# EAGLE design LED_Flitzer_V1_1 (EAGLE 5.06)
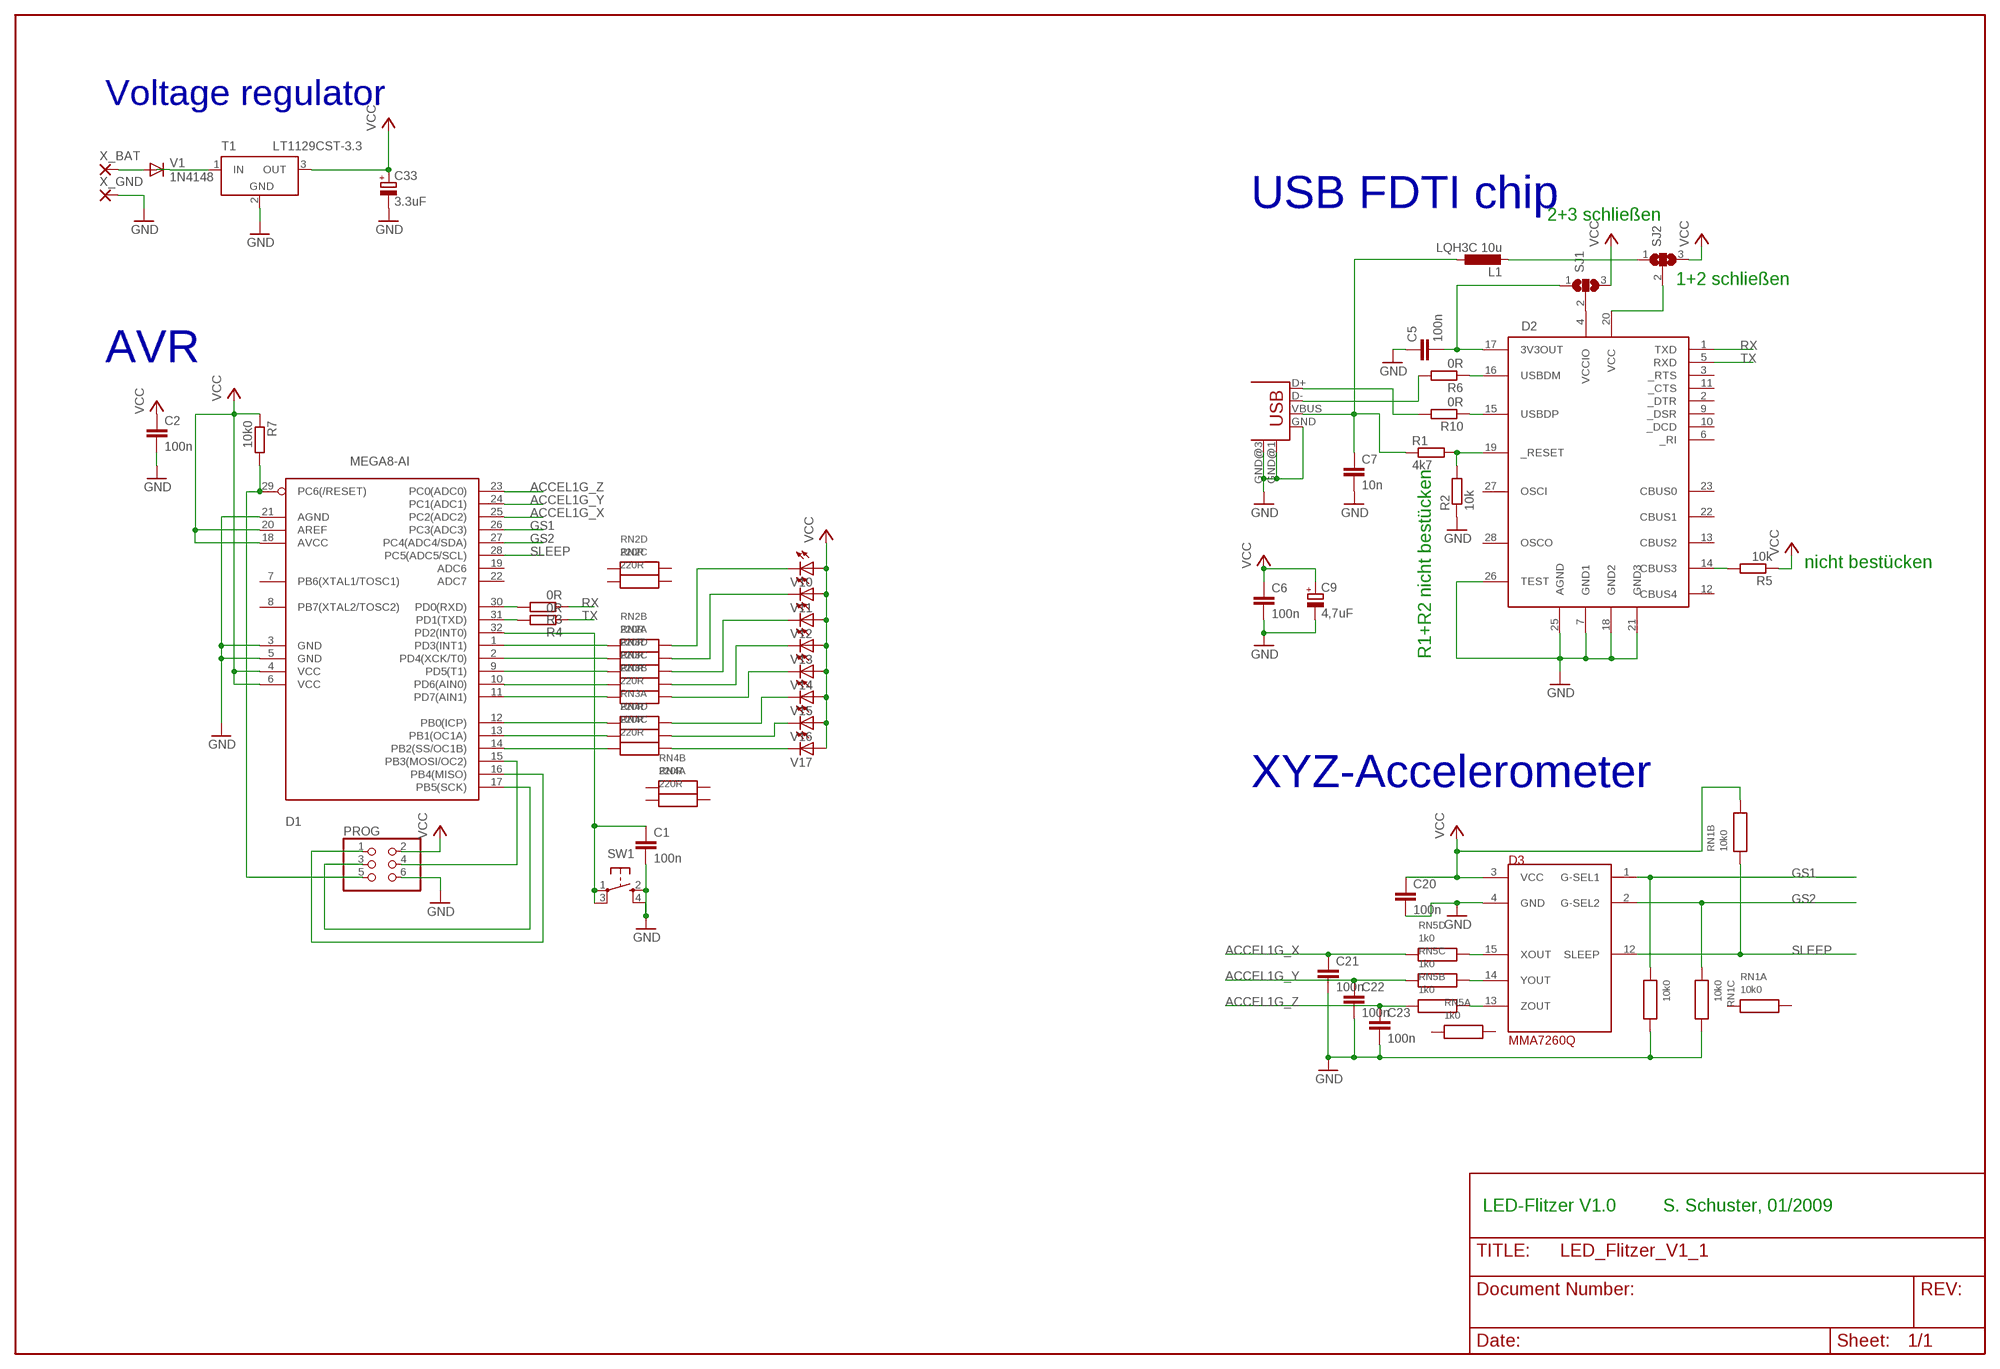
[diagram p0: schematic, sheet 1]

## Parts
C1  100n  C-EUC1206  [C1206]
C2  100n  C-EUC1206  [C1206]
C5  100n  C-EUC1206  [C1206]
C6  100n  C-EUC1206  [C1206]
C7  10n  C-EUC1206  [C1206]
C9  4,7uF  CPOL-EUCT6032  [CT6032]
C20  100n  C-EUC1206  [C1206]
C21  100n  C-EUC1206  [C1206]
C22  100n  C-EUC1206  [C1206]
C23  100n  C-EUC1206  [C1206]
C33  3.3uF  CPOL-EUCT6032  [CT6032]
D1  MEGA8-AI  [TQFP32-08]
D2  FT232RL  [SSOP28DB]
D3  MMA7260Q  [QFN16]
L1  LQH3C 10u  L-EUL3225P  [L3225P]
PROG  PINHD-2X3  [2X03]
R1  4k7  R-EU_M1206  [M1206]
R2  10k  R-EU_M1206  [M1206]
R3  0R  R-EU_M1206  [M1206]
R4  0R  R-EU_M1206  [M1206]
R5  10k  R-EU_M1206  [M1206]
R6  0R  R-EU_M1206  [M1206]
R7  10k0  R-EU_M1206  [M1206]
R10  0R  R-EU_M1206  [M1206]
RN1  10k0  4X1-12061206  [1206]
RN2  220R  4X1-12061206  [1206]
RN3  220R  4X1-12061206  [1206]
RN4  220R  4X1-12061206  [1206]
RN5  1k0  4X1-12061206  [1206]
SJ1  SJ2W  [SJ_2]
SJ2  SJ2W  [SJ_2]
SW1  CK_TACTSWITCHJ-LEAD  [CK_KT11_JM]
T1  LT1129CST-3.3  LT1129CST5  [SOT223]
USB1  USB BWM SMD  USB-MB-S  [USB-MB-S]
V1  1N4148  [DO35-10]
V10  LEDCHIPLED_1206  [CHIPLED_1206]
V11  LEDCHIPLED_1206  [CHIPLED_1206]
V12  LEDCHIPLED_1206  [CHIPLED_1206]
V13  LEDCHIPLED_1206  [CHIPLED_1206]
V14  LEDCHIPLED_1206  [CHIPLED_1206]
V15  LEDCHIPLED_1206  [CHIPLED_1206]
V16  LEDCHIPLED_1206  [CHIPLED_1206]
V17  LEDCHIPLED_1206  [CHIPLED_1206]
X_BAT  2,15/1,0  [2,15/1,0]
X_GND  2,15/1,0  [2,15/1,0]

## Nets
ACCEL1G_X: C21.1 D1.25(PC2(ADC2)) RN5.R4A(D:A)
ACCEL1G_Y: C22.1 D1.24(PC1(ADC1)) RN5.R3A(C:A)
ACCEL1G_Z: C23.1 D1.23(PC0(ADC0)) RN5.R2A(B:A)
GND [power]: C1.2 C2.2 C5.1 C6.2 C7.2 C9.- C20.2 C21.2 C22.2 C23.2 C33.- D1.3(GND) D1.5(GND) D1.21(AGND) D2.7(GND1) D2.18(GND2) D2.21(GND3) D2.25(AGND) D2.26(TEST) D3.4(GND) PROG.6 R2.1 RN1.R3B(C:B) RN1.R4B(D:B) SW1.2(S) SW1.4(S1) T1.2(GND) USB1.GND USB1.GND@1(GND) USB1.GND@3(GND) X_GND.1(P)
GS1: D1.26(PC3(ADC3)) D3.1(G-SEL1) RN1.R4A(D:A)
GS2: D1.27(PC4(ADC4/SDA)) D3.2(G-SEL2) RN1.R3A(C:A)
N$3: R6.2 USB1.D-
N$4: R10.2 USB1.D+
N$5: D1.30(PD0(RXD)) R3.2
N$6: D1.31(PD1(TXD)) R4.2
N$7: D1.1(PD3(INT1)) RN2.R2A(B:A)
N$8: D1.2(PD4(XCK/T0)) RN2.R1A(A:A)
N$9: D1.9(PD5(T1)) RN3.R4A(D:A)
N$10: D1.10(PD6(AIN0)) RN3.R3A(C:A)
N$11: D1.11(PD7(AIN1)) RN3.R2A(B:A)
N$12: D1.12(PB0(ICP)) RN3.R1A(A:A)
N$14: D2.20(VCC) SJ2.2
N$15: D1.15(PB3(MOSI/OC2)) PROG.4
N$16: D1.17(PB5(SCK)) PROG.3
N$17: C1.1 D1.32(PD2(INT0)) SW1.1(P) SW1.3(P1)
N$18: D1.29(PC6(/RESET)) PROG.5 R7.2
N$19: D1.16(PB4(MISO)) PROG.1
N$20: D1.13(PB1(OC1A)) RN4.R4A(D:A)
N$21: D1.14(PB2(SS/OC1B)) RN4.R3A(C:A)
N$24: D2.19(_RESET) R1.2 R2.2
N$27: RN2.R2B(B:B) V10.C
N$29: RN3.R4B(D:B) V12.C
N$30: RN3.R3B(C:B) V13.C
N$31: RN3.R2B(B:B) V14.C
N$32: RN3.R1B(A:B) V15.C
N$33: RN4.R4B(D:B) V16.C
N$34: RN4.R3B(C:B) V17.C
N$35: C7.1 L1.1 R1.1 USB1.VBUS
N$39: C5.2 D2.17(3V3OUT) SJ1.1
N$40: D2.14(CBUS3) R5.2
N$41: D2.16(USBDM) R6.1
N$42: D2.15(USBDP) R10.1
N$43 [power]: V1.A X_BAT.1(P)
N$44: L1.2 SJ2.1
N$45: D2.4(VCCIO) SJ1.2
N$46 [power]: T1.1(IN) V1.C
N$72: D3.15(XOUT) RN5.R4B(D:B)
N$73: D3.14(YOUT) RN5.R3B(C:B)
N$74: D3.13(ZOUT) RN5.R2B(B:B)
RX: D2.1(TXD) R3.1
SLEEP: D1.28(PC5(ADC5/SCL)) D3.12(SLEEP) RN1.R2A(B:A)
TX: D2.5(RXD) R4.1
V11: RN2.R1B(A:B) V11.C
VCC [power]: C2.1 C6.1 C9.+ C20.1 C33.+ D1.4(VCC) D1.6(VCC) D1.18(AVCC) D1.20(AREF) D3.3(VCC) PROG.2 R5.1 R7.1 RN1.R2B(B:B) SJ1.3 SJ2.3 T1.3(OUT) V10.A V11.A V12.A V13.A V14.A V15.A V16.A V17.A
Unconnected: D1.7(PB6(XTAL1/TOSC1)) D1.8(PB7(XTAL2/TOSC2)) D1.19(ADC6) D1.22(ADC7) D2.2(_DTR) D2.3(_RTS) D2.6(_RI) D2.9(_DSR) D2.10(_DCD) D2.11(_CTS) D2.12(CBUS4) D2.13(CBUS2) D2.22(CBUS1) D2.23(CBUS0) D2.27(OSCI) D2.28(OSCO) RN1.R1A(A:A) RN1.R1B(A:B) RN2.R3A(C:A) RN2.R3B(C:B) RN2.R4A(D:A) RN2.R4B(D:B) RN4.R1A(A:A) RN4.R1B(A:B) RN4.R2A(B:A) RN4.R2B(B:B) RN5.R1A(A:A) RN5.R1B(A:B)

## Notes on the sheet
- Voltage regulator
- USB FDTI chip
- 2+3 schließen
- 1+2 schließen
- AVR
- nicht bestücken
- R1+R2 nicht bestücken
- XYZ-Accelerometer
- LED-Flitzer V1.0 | S. Schuster, 01/2009

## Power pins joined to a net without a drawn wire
GND: T1.4(GND)

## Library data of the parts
C1 C2 C5-C7 C20-C23 = rcl:C-EU: CAPACITOR, European symbol
C9 C33 = rcl:CPOL-EU: POLARIZED CAPACITOR, European symbol
D1 = proj:MEGA8: MICROCONTROLLER 8 Kbytes FLASH 1 kbytes SRAM 512 bytes EEPROM USART 6-channel 10 bit ADC 2-channel 8 bit ADC
D2 = ftdichip:FT232RL: USB UART 4th Generation USB UART (USB <-> Serial) Controller
D3 = my_freescale_mma:MMA7260Q
L1 = rcl:L-EU: INDUCTOR, European symbol
PROG = proj:PINHD-2X3: PIN HEADER
R1-R7 R10 = rcl:R-EU_: RESISTOR, European symbol
RN1-RN5 = arrays:4X1-1206
SJ1 SJ2 = jumper:SJ2W: SMD solder JUMPER
SW1 = proj:CK_TACTSWITCH: C&K tactile switches
T1 = linear-technology:LT1129CST5: VOLTAGE REGULATOR with shutdown
USB1 = con-usb-2:USB: USB Connectors
V1 = diode:1N4148: DIODE
V10-V17 = proj:LED: LED
X_BAT X_GND = wirepad:2,15/1,0: THROUGH-HOLE PAD

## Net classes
1 power: width 0.305 mm, drill 0.61 mm

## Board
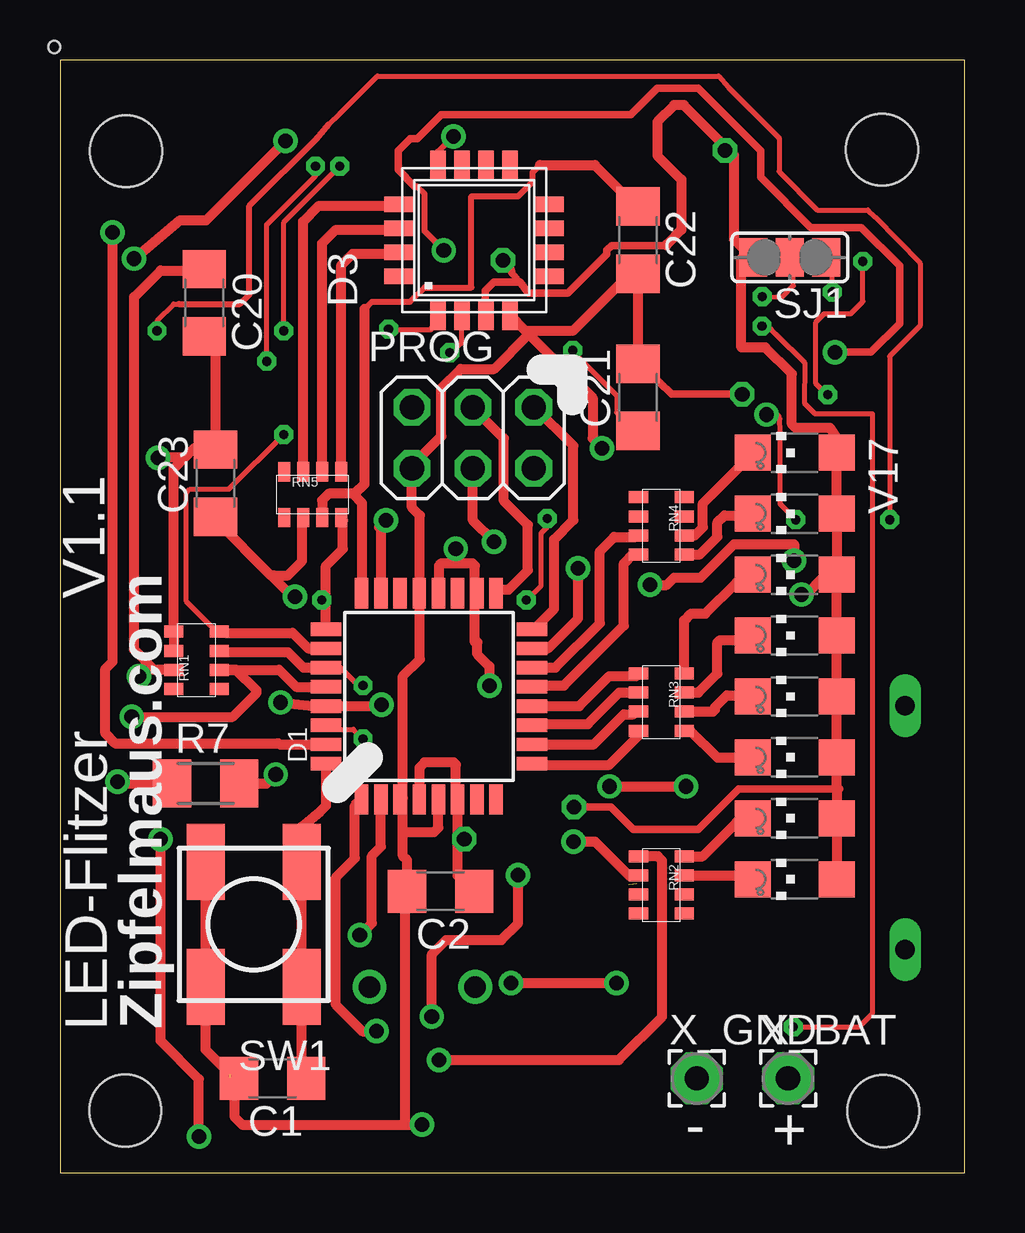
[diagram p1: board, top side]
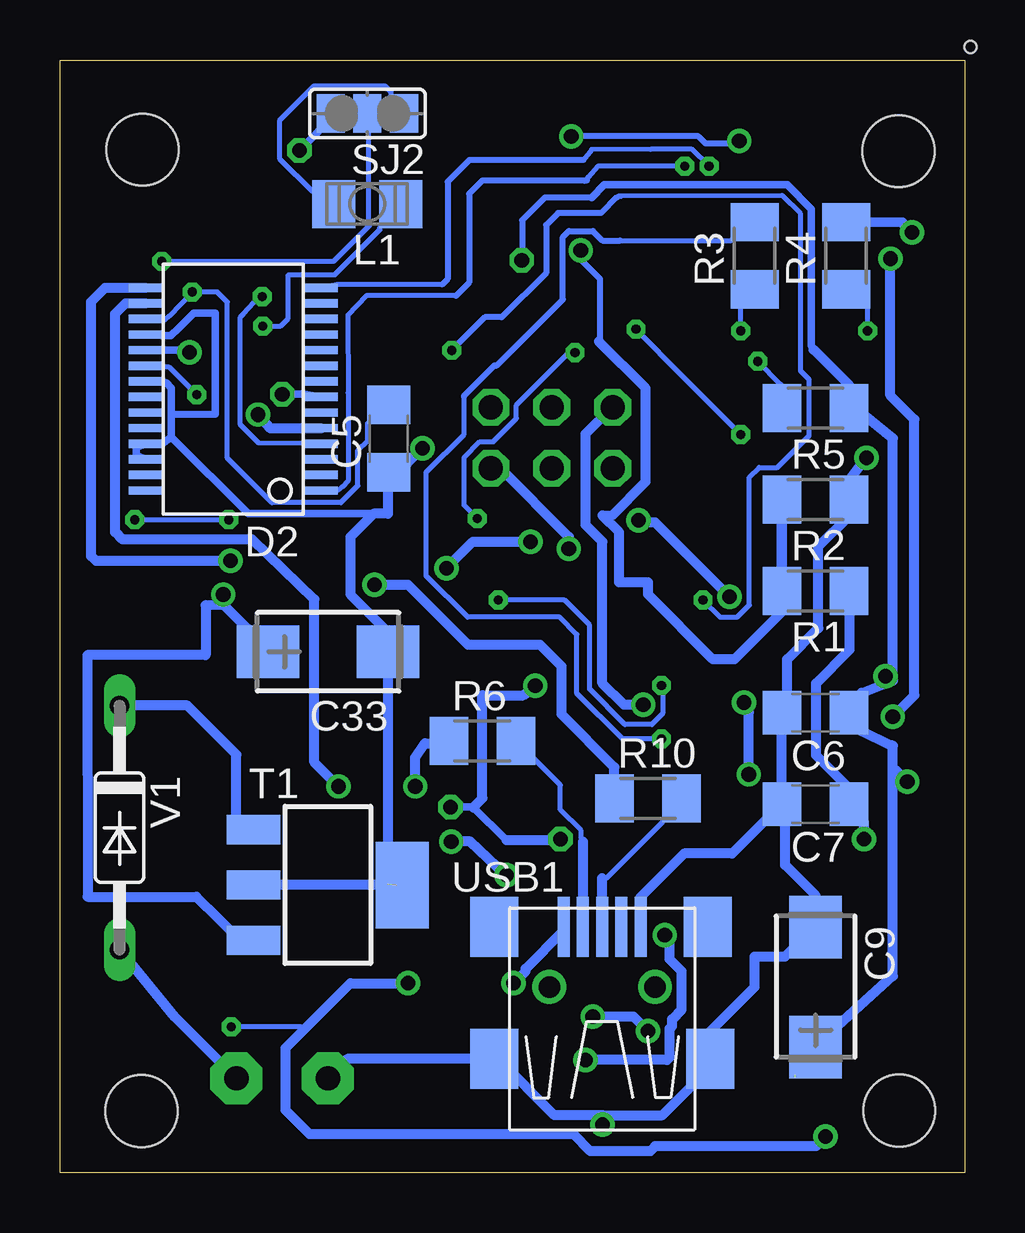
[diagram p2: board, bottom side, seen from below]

Size 37.69 x 46.38 mm. Coordinates in mm from the lower left corner, seen from the top.
Outline: 37.69,0 37.69,46.38 0,46.38 0,0 37.69,0
Copper layers (1*16): Top 0.035mm / dielectric 1.5mm / Bottom 0.035mm
Design rules "default": minimum track width 8mil, minimum drill 15mil, track to track 8mil, track to pad 8mil, pad to pad 8mil, via to via 8mil, smd to smd 8mil, copper to edge 40mil, drill to drill 8mil, minimum pad ring 10mil, minimum via ring 8mil, stop-mask expansion 4mil, vias tented up to drill 25mil, thermal gap 10mil
Holes 3 mm at 34.3,2.57 2.72,2.59 2.75,42.58 34.25,42.64
Holes 0.5 mm at -0.24,46.93

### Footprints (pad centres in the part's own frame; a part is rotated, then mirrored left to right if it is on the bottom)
C1206 = smd 1.6 x 1.8: 1 -1.4,0; 2 1.4,0
CT6032 = smd 2.6 x 2.2: + 2.5,0; - -2.5,0
TQFP32-08 = smd 1.27 x 0.559: 1 -4.293,2.8; 2 -4.293,2; 3 -4.293,1.2; 4 -4.293,0.4; 5 -4.293,-0.4; 6 -4.293,-1.2; 7 -4.293,-2; 8 -4.293,-2.8; 17 4.293,-2.8; 18 4.293,-2; 19 4.293,-1.2; 20 4.293,-0.4; 21 4.293,0.4; 22 4.293,1.2; 23 4.293,2; 24 4.293,2.8 | smd 0.559 x 1.27: 9 -2.8,-4.293; 10 -2,-4.293; 11 -1.2,-4.293; 12 -0.4,-4.293; 13 0.4,-4.293; 14 1.2,-4.293; 15 2,-4.293; 16 2.8,-4.293; 25 2.8,4.293; 26 2,4.293; 27 1.2,4.293; 28 0.4,4.293; 29 -0.4,4.293; 30 -1.2,4.293; 31 -2,4.293; 32 -2.8,4.293
SSOP28DB = smd 0.348 x 1.397: 1 -4.225,-3.656; 2 -3.575,-3.656; 3 -2.925,-3.656; 4 -2.275,-3.656; 5 -1.625,-3.656; 6 -0.975,-3.656; 7 -0.325,-3.656; 8 0.325,-3.656; 9 0.975,-3.656; 10 1.625,-3.656; 11 2.275,-3.656; 12 2.925,-3.656; 13 3.575,-3.656; 14 4.225,-3.656; 15 4.225,3.656; 16 3.575,3.656; 17 2.925,3.656; 18 2.275,3.656; 19 1.625,3.656; 20 0.975,3.656; 21 0.325,3.656; 22 -0.325,3.656; 23 -0.975,3.656; 24 -1.625,3.656; 25 -2.275,3.656; 26 -2.925,3.656; 27 -3.575,3.656; 28 -4.225,3.656
QFN16 = smd 1.27 x 0.635: 1 -3.1,1.5; 2 -3.1,0.5; 3 -3.1,-0.5; 4 -3.1,-1.5; 9 3.1,-1.5; 10 3.1,-0.5; 11 3.1,0.5; 12 3.1,1.5 | smd 0.635 x 1.27: 5 -1.5,-3.1; 6 -0.5,-3.1; 7 0.5,-3.1; 8 1.5,-3.1; 13 1.5,3.1; 14 0.5,3.1; 15 -0.5,3.1; 16 -1.5,3.1
L3225P = smd 1.8 x 2: 1 -1.4,0; 2 1.4,0
2X03 = drill 1.016 octagon: 1 -2.54,-1.27; 2 -2.54,1.27; 3 0,-1.27; 4 0,1.27; 5 2.54,-1.27; 6 2.54,1.27
M1206 = smd 1.6 x 2: 1 -1.4,0; 2 1.4,0
1206 = smd 0.5 x 0.8: R1A 0.318,-0.159; R1B 0.318,1.746; R2A 1.111,-0.159; R2B 1.111,1.746; R3A 1.905,-0.159; R3B 1.905,1.746; R4A 2.699,-0.159; R4B 2.699,1.746
SJ_2 = smd 1.168 x 1.6: 1 -1.524,0; 2 0,0; 3 1.524,0
CK_KT11_JM = smd 3.175 x 1.587: 1 -2.603,2; 2 -2.603,-2; 3 2.603,2; 4 2.603,-2
SOT223 = smd 1.219 x 2.235: 1 -2.311,-3.099; 2 0,-3.099; 3 2.311,-3.099 | smd 3.6 x 2.2: 4 0,3.099
USB-MB-S = smd 2.5 x 0.5: D+ 2.5,0; D- 2.5,0.8; GND 2.5,-1.6; ID 2.5,-0.8; VBUS 2.5,1.6 | smd 2.5 x 2: GND@1 -3,4.5; GND@2 2.5,4.5; GND@3 -3,-4.5; GND@4 2.5,-4.4 | drill 0.9 round: P$5 0,2.2; P$6 0,-2.2
DO35-10 = drill 0.813 long: A 5.08,0; C -5.08,0
CHIPLED_1206 = smd 1.5 x 1.5: A 0,-1.75; C 0,1.75
2,15/1,0 = drill 1.016 pad 2.159 octagon: 1 0,0

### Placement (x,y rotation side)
C1  8.86,3.93 180 top
C2  15.86,11.73 180 top
C5  23.99,30.6 90 bottom
C6  6.21,19.17 180 bottom
C7  6.21,15.36 180 bottom
C9  6.21,7.74 270 bottom
C20  6.01,36.26 270 top
C21  24.08,32.32 90 top
C22  24.08,38.87 270 top
C23  6.48,28.74 90 top
C33  26.53,21.71 180 bottom
D1  15.37,19.85 90 top
D2  30.47,32.66 90 bottom
D3  17.25,38.86 90 top
L1  24.89,40.38 180 bottom
PROG  17.2,30.63 180 top
R1  6.21,24.25 180 bottom
R2  6.21,28.06 180 bottom
R3  8.75,38.22 90 bottom
R4  4.94,38.22 90 bottom
R5  6.21,31.87 180 bottom
R6  20.09,17.99 0 bottom
R7  6.07,16.22 0 top
R10  13.19,15.6 0 bottom
RN1  6.48,19.85 90 top
RN2  24.26,13.5 270 top
RN3  24.26,21.12 270 top
RN4  24.26,28.47 270 top
RN5  9.02,27.47 0 top
SJ1  30.41,38.15 180 top
SJ2  24.88,44.15 180 bottom
SW1  8.07,10.35 270 top
T1  26.53,11.99 270 bottom
USB1  15.1,7.74 90 bottom
V1  35.21,14.38 270 bottom
V10  30.61,12.23 90 top
V11  30.61,14.77 90 top
V12  30.61,17.31 90 top
V13  30.61,19.85 90 top
V14  30.61,22.39 90 top
V15  30.61,24.93 90 top
V16  30.61,27.47 90 top
V17  30.61,30.01 90 top
X_BAT  30.34,3.93 0 top
X_GND  26.53,3.93 0 top

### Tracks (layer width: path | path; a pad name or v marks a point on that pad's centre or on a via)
ACCEL1G_X  (via drill 0.38)
  Top 0.203: v21.36,34.28 21.36,34.23 23.19,32.4 23.19,31.69 C21.1 | 11.08,23.86 v10.9,23.86
  Top 0.406: D1.25 11.08,23.86 11.08,25.29 11.79,26 11.79,27.2 11.72,27.27 RN5.R4A
  Bottom 0.203: 14.48,40.66 14.44,40.7 14.31,40.7 7.6,40.73 6.84,39.97 6.84,33.41 6.48,33.06 6.48,30.72 7.8,29.4 8.56,29.4 8.97,28.99 8.97,23.66 9.48,23.15 10.19,23.15 v10.9,23.86
  Bottom 0.254: 14.48,40.66 15.14,40 16.94,40 17.44,39.5 17.44,37.5 19.29,35.65 19.99,35.65 v21.36,34.28
ACCEL1G_Y
  Top 0.254: 12.69,36 12.99,36.3 14.59,36.3 15.19,36.9 17.14,36.9 17.14,40.7 19.09,40.7 19.69,41.3 19.69,41.7 19.99,42
  Top 0.406: 12.55,24.14 D1.24 12.57,24.28 12.59,24.3 12.59,27.9 12.19,28.3 | RN5.R3A 10.93,28.04 11.19,28.3 12.19,28.3 | 12.19,28.3 12.29,28.3 12.69,28.7 12.69,36 | C22.1 24.02,40.27 22.29,42 19.99,42
ACCEL1G_Z  (via drill 0.61)
  Top 0.406: C23.1 6.48,27.21 8.79,24.9 8.89,24.9 | 8.89,24.9 9.49,24.9 10.09,25.5 10.09,27.3 10.1,27.31 RN5.R2A | D1.23 13.37,26.9 13.29,26.9 v13.59,27.2 | 8.89,24.9 8.89,24.8 9.69,24 v9.79,24
  Bottom 0.406: v13.59,27.2 13.59,27.1 12.89,27.1 v9.79,24
GND  (via drill 0.61)  (2 unrouted)
  Top 0.305: v28.43,32.45 25.48,32.45 24.97,32.96 C21.2
  Top 0.406: C20.2 6.01,34.82 5.99,34.8 6.48,34.31 C23.2 | RN1.R3B 4.73,22.46 4.69,22.5 RN1.R4B 4.73,29.34 5.19,29.8 | C23.2 6.65,30.14 | C23.2 6.48,30.19 6.49,30.2 5.59,30.2 5.19,29.8 | 5.19,29.8 v4.09,29.8 | 24.09,37.5 24.08,37.49 C22.2 | C22.2 C21.2 | C22.2 23.76,37.47 21.39,35.1 19.39,35.1 | v22.59,30.2 22.19,30.6 22.19,32.3 19.54,34.95 | D3.4 18.75,35.74 19.39,35.1 | 19.54,34.95 19.39,35.1 | 19.54,34.95 18.09,33.5 16.69,33.5 15.89,32.7 15.89,30.7 14.66,29.47 PROG.6 14.66,27.73 14.99,27.4 14.99,24 | 14.97,24.02 D1.21 14.93,24.04 14.99,24 | 14.97,24.02 14.89,24.1 14.89,24.2 14.99,24.1 14.99,24 | 14.99,24 14.97,24.02 | 14.99,24 14.99,21.4 14.29,20.7 14.29,15.6 | D1.3 14.25,15.56 14.29,15.6 | D1.5 15.77,14.38 15.59,14.2 14.29,14.2 | 14.29,14.2 14.29,15.6 | 14.29,14.2 14.29,13.2 14.46,13.03 C2.2 14.46,11.99 14.32,12.13 14.32,11.87 14.39,11.6 14.39,2 | 6.07,12.8 SW1.2 | 6.07,12.8 6.09,12.8 | 6.07,12.8 6.07,7.62 6.09,7.6 6.07,7.6 | 14.39,2 v15.09,2 | 14.39,2 7.59,2 7.29,2.3 7.29,3.6 6.99,3.9 7.07,3.98 | 6.07,7.6 SW1.4 | 6.07,7.6 6.07,5.12 7.09,4.1 7.07,4.08 7.22,3.93 C1.2
  Bottom 0.305: D2.18 33.46,34.89 33.09,34.89 32.74,35.2 32.11,35.83 31.23,35.83 31.23,31.62 33.05,31.6 33.05,32.7 | D2.26 34.52,29.91 34.52,30.21 D2.25 33.46,30.36 33.05,30.67 | D2.21 33.46,33.01 33.25,32.91 33.05,32.7 | D2.7 27.51,32.45 v28.43,32.45 | 33.05,30.67 33.05,32.7 | 33.05,30.67 29.85,27.47 24.03,27.47
  Bottom 0.406: 24.03,12.04 C33.- 24.03,22.54 25.59,24.1 25.59,26.5 24.62,27.47 24.03,27.47 24.03,29 | C5.1 23.99,29.3 24.03,29.26 24.03,29 | v4.09,29.8 4.81,28.88 R2.1 4.81,27.38 6.09,26.1 6.09,22.7 7.39,21.4 7.39,19.4 7.49,19.3 7.49,19.17 | 24.03,29 23.79,29 v22.59,30.2 | 7.49,19.17 C6.2 | 7.49,19.17 7.48,19.17 7.61,19.04 C7.2 7.48,15.36 7.48,15.3 | USB1.GND 13.5,11.49 11.69,13.3 9.69,13.3 7.69,15.3 7.48,15.3 | 7.48,15.3 7.48,12.82 6.21,11.55 6.21,10.28 | 6.21,10.28 C9.- | 6.21,10.28 7.48,9.01 8.75,9.01 8.75,7.74 10.6,5.89 USB1.GND@3 10.6,4.39 12.59,2.4 15.09,2.4 | X_GND.1 25.72,4.74 USB1.GND@1 | 20.18,5.2 19.72,4.74 USB1.GND@1 | USB1.GND@1 19.43,4.74 17.09,2.4 15.09,2.4 | v15.09,2 15.09,2.4 | 29.63,12.14 29.69,12.2 | 29.63,12.14 T1.2 | 29.63,12.14 29.48,11.99 23.69,11.99 | 23.69,11.99 23.69,11.7 | T1.4 23.69,11.99
GS1  (via drill 0.38)
  Top 0.203: v13.69,35.16 13.69,35.1 13.73,35.14 15.47,35.14 D3.1 | v9.33,30.77 7.04,28.49 5.41,28.49 5.26,28.33 5.26,23.81 6.28,22.8 RN1.R4A
  Top 0.406: D1.26 10.34,21.85 9.69,22.5 6.89,22.5 6.79,22.6 6.74,22.55 RN1.R4A
  Bottom 0.203: v13.69,35.16 11.71,33.16 v9.33,30.77
GS2  (via drill 0.38)
  Top 0.203: v16.23,34.18 16.74,34.58 16.74,35.34 D3.2 | v20.3,27.27 20.3,26.91 20.04,26.66 20.04,24.47 v19.43,23.86 | v12.63,20.31 12.42,20.31 11.66,21.07 D1.27
  Top 0.406: RN1.R3A 6.64,21.75 6.59,21.7 9.49,21.7 10.14,21.05 D1.27 11.24,21.05 11.29,21.1
  Bottom 0.203: v16.23,34.18 16.49,34.18 18.67,31.99 18.67,31.43 19.64,30.47 20.2,30.47 20.86,29.81 20.86,27.83 v20.3,27.27 | v19.43,23.86 16.67,23.86 15.62,22.82 15.62,20.16 14.15,18.68 13.03,18.68 12.58,19.14 12.58,20.26 v12.63,20.31
N$3
  Bottom 0.203: R6.2 16.84,16.15 16.84,15.13 15.98,14.26 15.98,13.96 15.89,13.8
  Bottom 0.406: USB1.D- 15.95,10.24 15.89,10.3 15.89,13.8
N$4
  Bottom 0.203: R10.2 12.58,14.62 14.91,12.28 15.1,12.28
  Bottom 0.406: USB1.D+ 15.1,12.28
N$5  (via drill 0.38)
  Top 0.203: v12.63,18.07 12.22,18.48 11.66,18.48 D1.30
  Bottom 0.203: v12.63,18.07 14.25,18.07 16.15,19.97 16.15,22.44 16.87,23.15 20.7,23.15 22.43,24.88 22.43,29.2 20.86,30.77 20.86,32.35 | 14.35,38.85 9.73,38.85 R3.2
  Bottom 0.254: 14.35,38.85 15.09,38.85 15.49,39.25 16.49,39.25 16.74,39 16.74,36.4 19.49,33.65 19.59,33.65 20.86,32.38 20.86,32.35
N$6  (via drill 0.61)
  Top 0.406: D1.31 9.14,17.85 9.09,17.9 2.29,17.9 1.89,18.3 1.89,21 2.19,21.3 v2.19,39.2
  Bottom 0.406: R4.2 4.11,39.62 2.59,39.6 v2.19,39.2
N$7  (via drill 0.61)
  Top 0.406: RN2.R2A 23.7,12.39 22.29,13.8 v21.39,13.8 | v19.09,12.4 19.09,10.4 18.39,9.7 16.09,9.7 15.49,9.1 v15.49,6.5 | v13.19,5.9 12.59,5.9 11.49,7 11.49,12.3 12.29,13.1 12.29,15.3 12.55,15.56 D1.1
  Bottom 0.406: v21.39,13.8 20.59,13.8 v19.09,12.4 | v15.49,6.5 13.79,6.5 v13.19,5.9
N$8  (via drill 0.61)
  Top 0.406: RN2.R1A 24.91,13.18 25.09,13 25.09,6.5 23.29,4.7 v15.79,4.7 | D1.2 13.37,13.58 12.99,13.2 12.99,10.4 v12.49,9.9 12.39,9.8
  Bottom 0.406: v15.79,4.7 12.39,4.7 12.29,4.8 12.29,6 12.19,6.1 12.19,6.4 11.79,6.8 11.79,8.4 12.29,8.9 12.29,9.7 v12.49,9.9
N$9
  Top 0.406: RN3.R4A 24.1,18.21 22.89,17 19.69,17 19.66,17.03 D1.9
N$10
  Top 0.406: D1.10 22.24,17.85 23.49,19.1 23.89,19.1 24,19.21 RN3.R3A
N$11
  Top 0.406: RN3.R2A 23.3,20.01 21.99,18.7 19.79,18.7 19.69,18.6 19.66,18.63 D1.11
N$12
  Top 0.406: D1.12 21.64,19.45 22.89,20.7 23.99,20.7 RN3.R1A
N$14  (via drill 0.38)
  Top 0.203: v31.99,32.42 31.99,32.4 31.49,32.9 31.49,35.45 31.84,35.8 32.94,35.8 33.46,36.31 v33.46,37.99
  Bottom 0.203: v31.99,32.42 33.15,33.57 33.46,33.57 D2.20 | v33.46,37.99 26.29,37.99 24.77,39.51 24.82,39.56 24.82,43.37 SJ2.2
N$15  (via drill 0.61)
  Top 0.406: D1.15 20.34,21.85 21.59,23.1 v21.59,25.2 | PROG.4 17.2,27.19 v18.09,26.3
  Bottom 0.406: v18.09,26.3 20.49,26.3 v21.59,25.2
N$16
  Top 0.406: D1.17 18.17,24.18 18.29,24.3 18.69,24.3 19.49,25.1 19.49,27 18.49,28 18.49,30.6 PROG.3
N$17
  Top 0.406: D1.32 11.08,17.01 11.09,17 11.09,15.3 10.84,15.05 10.07,14.42 SW1.1 10.07,7.92 10.09,7.9 10.07,7.88 SW1.3 10.07,4.98 10.09,3.8 10.13,3.8 C1.1
N$18  (via drill 0.61)
  Top 0.406: v13.39,19.5 13.34,19.45 D1.29 11.08,19.41 11.09,19.4 v9.19,19.6 | R7.2 8.61,16.22 v8.99,16.6
  Bottom 0.406: v13.39,19.5 14.19,19.5 15.09,20.4 15.09,26.3 15.79,27 15.79,30.8 14.69,31.9 PROG.5 | v8.99,16.6 8.99,19.2 v9.19,19.6
N$19
  Top 0.406: D1.16 19.74,22.65 20.59,23.5 20.59,26.4 21.39,27.2 21.39,30.3 19.79,31.9 PROG.1
N$20
  Top 0.406: D1.13 19.64,20.25 19.59,20.3 20.99,20.3 23.49,22.8 23.49,25.4 23.89,25.8 23.92,25.77 RN4.R4A
N$21
  Top 0.406: D1.14 20.64,21.05 22.49,22.9 22.49,25.9 23.09,26.5 23.99,26.5 24.09,26.6 24.1,26.59 RN4.R3A
N$24  (via drill 0.61)
  Top 0.254: 14.79,41.1 14.89,41.1 15.19,40.8 15.19,39.25 v15.99,38.45
  Top 0.305: v32.29,34.2 33.79,34.2 34.99,35.4 34.99,37.8 33.39,39.4 31.29,39.4 29.19,41.5 29.19,42.6 26.59,45.2 24.89,45.2 23.79,44.1 15.89,44.1 14.89,43.1 14.59,43.1 14.09,42.6 14.09,41.8 14.79,41.1
  Bottom 0.254: 15.24,34.65 15.19,34.7 15.19,37.25 15.99,38.05 v15.99,38.45
  Bottom 0.305: D2.19 32.8,34.28 v32.29,34.2
  Bottom 0.406: R1.2 7.61,24.28 7.59,24.3 7.61,24.32 R2.2 7.61,23.38 9.59,21.4 10.49,21.4 13.19,24.1 13.19,24.6 14.39,24.6 14.39,26.7 15.09,27.4 14.69,27.4 13.29,28.8 13.29,32.7 15.24,34.65
N$27
  Top 0.406: V10.C 28.86,12.17 28.79,12.1 28.5,12.39 RN2.R2B
N$29
  Top 0.406: RN3.R4B 26.27,18.42 27.39,17.3 28.69,17.3 28.79,17.2 28.86,17.27 V12.C
N$30
  Top 0.406: RN3.R3B 27.2,19.21 27.29,19.3 27.29,19.4 27.79,19.9 28.99,19.9 28.94,19.85 V13.C
N$31
  Top 0.406: RN3.R2B 26.6,20.01 27.39,20.8 27.39,22.1 27.49,22.2 28.79,22.2 28.98,22.39 | 28.98,22.39 28.99,22.4 | 28.98,22.39 V14.C
N$32
  Top 0.406: RN3.R1B 26.01,23.02 26.29,23.3 26.89,23.3 28.19,24.6 28.59,24.6 28.89,24.9 V15.C
N$33
  Top 0.406: RN4.R4B 26.66,25.77 27.39,26.5 27.39,27.1 27.69,27.4 28.79,27.4 V16.C
N$34
  Top 0.406: RN4.R3B 26.45,26.57 26.79,26.9 26.79,27.9 28.86,29.97 V17.C
N$35  (via drill 0.38, 0.61)
  Top 0.203: v29.25,35.29 29.49,35.3 29.85,34.94 31.05,33.74 31.04,32.05 31.47,31.62 33.86,31.62 33.86,6.64 33.3,6.08 v30.56,6.08
  Top 0.406: v23.19,7.9 v18.79,7.9 | v5.79,1.5 5.79,3.9 4.19,5.5 v4.19,13.9
  Bottom 0.203: v29.25,35.29 28.5,35.29 28.19,35.6 28.19,37.4 28.16,37.43 26.24,37.43 24.36,39.31 24.36,39.41 L1.1 | v30.56,6.08 27.66,6.08 27.54,5.96
  Bottom 0.406: R1.1 4.81,24.28 4.79,24.3 4.79,21.8 6.19,20.4 6.19,17.4 4.81,16.02 C7.1 4.81,15.22 4.19,14.6 v4.19,13.9 | USB1.VBUS 16.7,10.09 18.29,8.5 18.29,8.4 v18.79,7.9 | v23.19,7.9 25.59,7.9 27.54,5.96 28.29,5.2 28.29,2.6 27.29,1.6 16.29,1.6 15.59,0.9 13.09,0.9 12.89,1.1 6.19,1.1 v5.79,1.5
N$39  (via drill 0.38)
  Top 0.203: v32.19,36.71 32.19,37.38 SJ1.1
  Bottom 0.203: D2.17 33.3,35.55 33.15,35.7 v32.19,36.71 31.13,36.7 30.72,36.29 30.72,29.78 28.86,27.93 25.99,27.93 25.28,28.64 25.28,30.11 24.87,30.52 24.87,31.23 C5.2
N$40  (via drill 0.38)
  Top 0.203: v10.65,41.95 10.65,41.54 8.61,39.51 v8.61,33.82
  Bottom 0.203: 21.77,37.02 26.14,37.02 D2.14 | 15.89,42.2 15.54,42.65 13.08,42.66 11.36,42.66 v10.65,41.95 | v8.61,33.82 7.65,32.85 R5.2
  Bottom 0.254: 15.89,42.2 20.64,42.2 21.54,41.3 21.54,37.25 21.77,37.02
N$41  (via drill 0.61)
  Top 0.406: v22.89,16.1 v26.09,16.1
  Bottom 0.406: D2.16 34.96,36.23 35.39,35.8 35.39,26.7 35.09,26.4 29.69,26.4 27.09,23.9 27.09,17.1 v26.09,16.1 | v22.89,16.1 22.89,17.3 22.49,17.9 21.59,17.9 R6.1
N$42  (via drill 0.61)
  Top 0.406: v30.59,25.5 30.59,26.2 28.09,26.2 26.69,24.8 25.59,24.8 25.29,24.5 v24.59,24.5
  Bottom 0.406: R10.1 14.59,16.9 16.79,19.1 16.79,21.1 17.69,22 20.69,22 23.19,24.5 v24.59,24.5 | D2.15 35.8,36.88 36.39,36.3 36.39,25.7 36.19,25.5 v30.59,25.5
N$43
  Bottom 0.406: V1.A 32.88,6.47 X_BAT.1
N$44
  Bottom 0.203: SJ2.1 23.9,44.95 23.9,45.05 24.16,45.3 27.11,45.3 28.53,43.88 28.53,42.25 27.16,40.88 L1.2
N$45  (via drill 0.38)
  Top 0.203: v29.26,36.51 30.09,36.5 30.56,36.97 30.56,37.38 SJ1.2
  Bottom 0.203: v29.26,36.51 29.38,36.51 30.04,35.8 30.18,35.66 30.18,31.18 29.41,30.42 D2.4
N$46
  Bottom 0.406: T1.1 29.63,14.26 29.69,14.2 30.02,14.53 30.34,14.53 30.34,17.43 32.38,19.47 35.37,19.47 35.36,19.46 V1.C
N$72
  Top 0.406: RN5.R4B 11.72,37.83 12.19,38.3 14.19,38.3 14.15,38.34 D3.15
N$73
  Top 0.406: RN5.R3B 10.93,38.73 11.49,39.3 14.09,39.3 D3.14
N$74
  Top 0.406: RN5.R2B 10.13,39.64 10.79,40.3 14.09,40.3 D3.13
RX  (via drill 0.38)
  Top 0.203: v11.66,41.95 9.33,39.61 v9.33,35.09
  Bottom 0.203: v11.66,41.95 15.29,41.95 15.69,41.5 15.83,41.33 | v9.33,35.09 9.33,36.05 R3.1 | D2.1 26.12,28.44 25.94,28.59 25.68,28.84 25.68,32.5 25.69,35.75 24.94,36.55 21.19,36.55
  Bottom 0.254: 21.19,36.55 20.64,37.1 20.64,40.8 20.09,41.35 15.74,41.35 15.83,41.36 15.83,41.33
S$2
  Top 0.406: 23.99,10.8
SLEEP  (via drill 0.61)
  Top 0.254: D3.12 15.75,42.56 v16.39,43.2
  Top 0.406: D1.28 9.84,20.25 9.13,20.96 RN1.R2A 7.33,20.96 8.19,20.1 8.19,20 7.19,19 v2.99,19 | v9.39,43 6.09,39.7 4.99,39.7 v3.09,38.1
  Bottom 0.254: v16.39,43.2 11.09,43.2 10.79,42.9 9.49,42.9 v9.39,43
  Bottom 0.406: v3.09,38.1 3.09,32.4 2.09,31.4 2.09,19.9 v2.99,19
TX  (via drill 0.38, 0.61)
  Top 0.203: 4.96,36.2 4.73,36.2 4.06,35.53 v4.04,35.09 | v30.66,27.22 30,27.88 30,30.87 30,31.43 29.95,31.58 v29.44,31.6 | v34.57,27.22 34.57,34.03 35.84,35.3 35.84,37.91 33.96,39.83 33.66,40.13 31.56,40.13 29.96,41.73 29.96,43.13 27.84,45.25 27.44,45.71 13.23,45.71 11.65,44.13 11.19,43.7
  Top 0.254: 4.96,36.2 7.49,36.2 7.89,36.6 7.89,40.3 10.69,43.1 11.19,43.7
  Top 0.406: v29.44,31.6 29.44,31.65
  Bottom 0.203: v4.04,35.09 4.04,36.05 R4.1 | v34.57,27.22 v30.66,27.22
  Bottom 0.406: D2.5 28.92,31.04 v29.44,31.6
V11
  Top 0.406: RN2.R1B 26.77,13.18 28.19,14.6 28.69,14.6 V11.C 28.89,14.8
VCC  (via drill 0.61)
  Top 0.305: 16.57,13.91 v16.84,13.91 | v21.41,15.24 22.95,15.24 23.89,14.3 26.59,14.3 28.29,16 32.49,16 32.45,16.04 32.36,16.04 | 27.8,42.69 v27.71,42.61 | 25.28,38.65 22.99,38.65 22.79,38.44 22.79,38.29 21.16,36.66 19.54,36.66 19.43,36.77 19.51,36.67 | D3.3 17.71,36.16 17.71,36.76 18.08,37.11 19.17,37.12 19.51,36.67 | 19.51,36.67 18.81,37.52 18.79,37.7 v18.45,38.03
  Top 0.406: D1.20 15.77,24.48 15.79,24.5 15.79,25.3 15.89,25.4 16.49,25.4 | 16.49,25.4 v16.49,26 | 17.39,24.3 17.37,24.28 D1.18 17.37,24.08 17.29,24 | D1.4 14.97,16.88 15.19,17.1 16.39,17.1 16.49,17 16.49,15.8 16.57,15.72 D1.6 16.57,13.91 16.57,12.38 16.99,12 16.77,11.82 16.86,11.73 C2.1 | 16.49,25.4 17.19,25.4 17.29,25.3 17.29,24 | 17.29,24 17.29,22.1 17.39,22.1 17.39,21.6 17.89,21.1 v17.89,20.3 | 32.32,12.23 32.29,12.2 | 32.32,12.23 V10.A | 32.32,12.23 32.36,12.27 V11.A | 32.29,14.5 32.36,14.57 V11.A | V11.A 32.36,16.04 V12.A | 32.39,17.1 32.36,17.13 V12.A | V12.A V13.A 32.34,19.85 32.29,19.9 32.36,19.97 V14.A | 32.39,22.1 32.36,22.13 V14.A | V14.A V15.A 32.36,24.83 32.39,24.8 | v30.89,24.1 31.09,24.1 31.79,24.8 32.39,24.8 | 32.39,24.8 32.39,27.2 32.36,27.23 | 32.36,27.23 V16.A | 32.36,27.23 V17.A 32.36,30.63 32.09,31.04 30.65,31.04 30.49,31.2 30.49,33.3 29.39,34.4 28.39,34.4 28.39,38.1 28.89,38.1 SJ1.3 28.89,38.1 | 28.89,38.1 | 28.89,38.1 28.09,38.9 28.09,42.4 27.8,42.69 25.99,44.5 25.59,44.5 24.89,43.8 24.89,42.4 25.89,41.4 25.89,39.3 25.28,38.69 25.28,38.65 | 6.05,37.66 C20.1 6.01,37.68 5.99,37.7 5.89,37.6 4.19,37.6 3.09,36.5 3.09,21.8 3.93,20.96 RN1.R2B 3.55,20.96 v3.29,20.7 | R7.1 2.47,16.22 v2.39,16.3
  Bottom 0.254: 18.34,38.03 18.34,38.05 18.49,37.9 18.49,37.95 18.44,38 18.44,39.7 17.49,40.65 15.54,40.65 | C6.1 4.81,19.13 4.29,19.13 4.29,18.4
  Bottom 0.305: 19.09,13.87 20.47,15.22 20.61,15.25 v21.41,15.24 | SJ2.3 26.95,43.37 v27.71,42.61 | 18.34,38.03 v18.45,38.03 | 15.54,40.65 15,41.19 7.39,41.19 6.38,40.17 6.38,34.48 6.29,34.3
  Bottom 0.406: PROG.2 19.35,29.36 16.49,26.5 v16.49,26 | v16.84,13.91 16.8,13.91 16.79,13.9 16.82,13.87 19.09,13.87 | v17.89,20.3 18.39,19.9 20.09,19.9 20.09,15.6 20.47,15.22 | T1.3 30.17,9.68 32.01,11.5 36.54,11.5 36.55,21.57 31.62,21.57 31.62,23.66 30.84,23.65 | C33.+ 29.03,21.84 30.84,23.65 | 30.84,23.65 30.79,23.7 30.89,23.8 v30.89,24.1 | 6.29,34.3 4.79,32.8 4.79,31.9 4.69,31.8 4.69,31.87 | 4.69,31.87 R5.1 | 4.69,31.87 4.56,31.87 2.99,30.6 2.99,20.5 | C6.1 | 2.99,20.5 v3.29,20.7 | 2.99,20.5 3.29,20.4 4.29,20 4.29,18.4 3.09,17.8 2.99,17.8 2.99,16.8 | v2.39,16.3 2.89,16.8 2.99,16.8 | 2.99,16.8 2.99,8.2 6.21,5.28 C9.+

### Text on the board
tPlace: V1.1 | LED-Flitzer | Zipfelmaus.com | - | +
